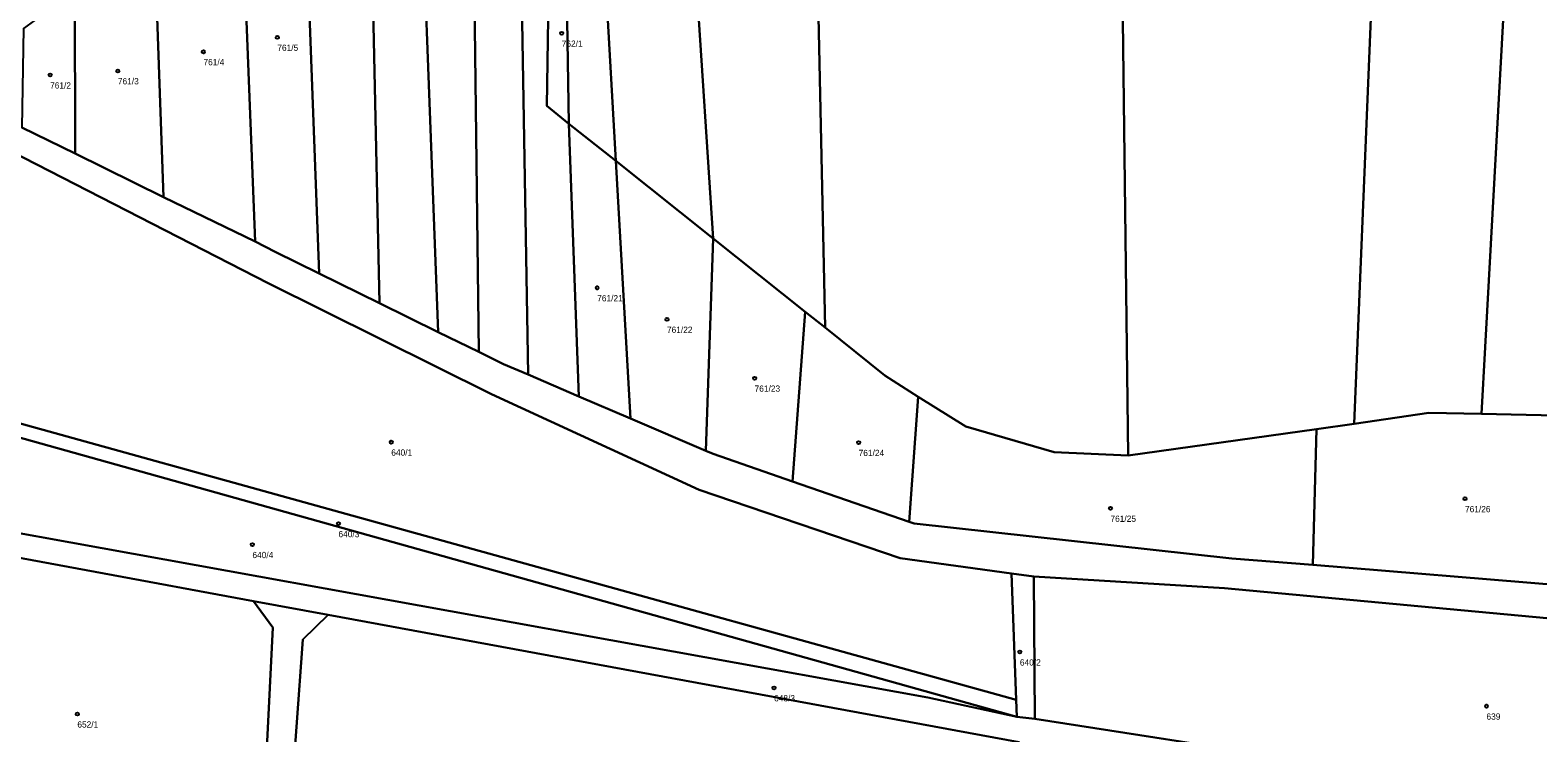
# Model space of a CAD drawing. Extents: x -587171 to -555306, y -1167727 to -1074732.
# Drawn here: x -586119 to -585877.6, y -1165348.1 to -1165235.6 of the extents above; entities that cross this region are included whole.
import ezdxf

# ---------------------------------------------------------------- set-up
doc = ezdxf.new("R2010")
doc.units = 0
doc.layers.add('Definiční body', color=7, linetype='Continuous')
doc.layers.add('Polygon parcely', color=7, linetype='Continuous')

msp = doc.modelspace()

# ---------------------------------------------------------------- linework, layer by layer
at = {"layer": 'Definiční body'}
for centre in [(-586033.93, -1165236.09), (-586079.47, -1165236.74), (-586091.3, -1165239.05), (-586115.85, -1165242.77), (-586105, -1165242.11), (-586028.25, -1165276.85), (-586017.08, -1165281.89), (-586003.05, -1165291.32), (-586061.22, -1165301.55), (-585986.39, -1165301.62), (-585889.3, -1165310.61), (-585946.07, -1165312.15), (-586069.68, -1165314.61), (-586083.46, -1165317.96), (-585960.57, -1165335.16), (-585999.93, -1165340.9), (-585885.86, -1165343.83), (-586111.49, -1165345.09)]:
    msp.add_circle(centre, 0.25, dxfattribs=at)
at = {"layer": 'Polygon parcely'}
for points in [[(-585886.63, -1165297.03), (-585876.95, -1165120.35), (-585894.18, -1165113.04), (-585883.91, -1165096.03), (-585896.44, -1165086.92), (-585882.93, -1165070.13), (-585873.52, -1165060.03), (-585881.75, -1165054.17), (-585897.71, -1165067.32), (-585902.01, -1165176.43), (-585907.05, -1165298.6), (-585895.08, -1165296.86)], [(-585907.05, -1165298.6), (-585902.01, -1165176.43), (-585897.71, -1165067.32), (-585909.33, -1165075.43), (-585909.82, -1165089.08), (-585929.67, -1165104.07), (-585945.54, -1165116.26), (-585943.24, -1165303.67), (-585913.05, -1165299.45)], [(-585978.48, -1165138.78), (-585981.42, -1165148.71), (-585993.8, -1165160.54), (-585993.37, -1165208.49), (-585991.77, -1165283.22), (-585982.19, -1165290.86), (-585976.85, -1165294.27), (-585969.25, -1165299.02), (-585955.07, -1165303.18), (-585943.24, -1165303.67), (-585945.54, -1165116.26), (-585965.05, -1165130.07)], [(-585864.03, -1165297.55), (-585856.06, -1165132.46), (-585873.96, -1165121.53), (-585876.95, -1165120.35), (-585886.63, -1165297.03), (-585872.33, -1165297.33)], [(-585993.37, -1165208.49), (-585993.8, -1165160.54), (-586000.81, -1165166.93), (-586005.94, -1165171.23), (-586011.22, -1165175.11), (-586011.11, -1165180.26), (-586012.43, -1165227.35), (-586009.68, -1165268.95), (-585994.93, -1165280.7), (-585991.77, -1165283.22)], [(-586033.79, -1165190.21), (-586034.18, -1165166.72), (-586040.52, -1165172.08), (-586040.27, -1165234.18), (-586039.3, -1165290.74), (-586031.18, -1165294.22), (-586032.77, -1165250.56), (-586036.34, -1165247.72), (-586035.46, -1165191.62)], [(-586039.3, -1165290.74), (-586040.27, -1165234.18), (-586040.52, -1165172.08), (-586048.55, -1165178.86), (-586047.22, -1165287.1), (-586043.25, -1165289.05)], [(-586047.22, -1165287.1), (-586048.55, -1165178.86), (-586057.39, -1165186.33), (-586053.71, -1165283.92)], [(-586012.43, -1165227.35), (-586011.11, -1165180.26), (-586026.17, -1165189.55), (-586026.83, -1165229.24), (-586025.28, -1165256.53), (-586009.68, -1165268.95)], [(-586057.39, -1165186.33), (-586064.99, -1165192.75), (-586063.1, -1165279.31), (-586053.71, -1165283.92)], [(-586025.28, -1165256.53), (-586026.83, -1165229.24), (-586026.17, -1165189.55), (-586033.72, -1165194.21), (-586032.77, -1165250.56)], [(-586036.34, -1165247.72), (-586032.77, -1165250.56), (-586033.72, -1165194.21), (-586033.79, -1165190.21), (-586035.46, -1165191.62)], [(-586063.1, -1165279.31), (-586064.99, -1165192.75), (-586075.49, -1165201.63), (-586072.78, -1165274.55)], [(-586072.78, -1165274.55), (-586075.49, -1165201.63), (-586082.38, -1165207.46), (-586085.35, -1165209.65), (-586083.03, -1165269.44), (-586079.8, -1165271.1)], [(-586083.03, -1165269.44), (-586085.35, -1165209.65), (-586099.19, -1165219.88), (-586097.7, -1165262.31)], [(-586097.7, -1165262.31), (-586099.19, -1165219.88), (-586111.91, -1165229.28), (-586111.83, -1165255.36)], [(-586111.83, -1165255.36), (-586111.91, -1165229.28), (-586120.11, -1165235.33), (-586120.4, -1165251.15)], [(-585961.16, -1165342.8), (-585961.9, -1165322.59), (-585979.72, -1165320.1), (-586011.93, -1165309.16), (-586045.19, -1165293.88), (-586080.96, -1165276.08), (-586142.78, -1165244.37), (-586142.51, -1165291.18), (-586142.77, -1165292.42)], [(-586022.93, -1165297.76), (-586025.28, -1165256.53), (-586032.77, -1165250.56), (-586031.18, -1165294.22)], [(-586025.28, -1165256.53), (-586022.93, -1165297.76), (-586010.87, -1165302.94), (-586009.68, -1165268.95)], [(-585997, -1165307.83), (-585994.93, -1165280.7), (-586009.68, -1165268.95), (-586010.87, -1165302.94), (-586009.69, -1165303.44)], [(-585982.19, -1165290.86), (-585991.77, -1165283.22), (-585994.93, -1165280.7), (-585997, -1165307.83), (-585978.32, -1165314.29), (-585976.85, -1165294.27)], [(-585961.06, -1165345.54), (-585961.16, -1165342.8), (-586142.77, -1165292.42), (-586143.09, -1165293.97), (-586143.12, -1165294.54)], [(-585975.3, -1165342.45), (-585961.06, -1165345.54), (-586143.12, -1165294.54), (-586143.87, -1165307.19), (-586138.24, -1165312.97)], [(-585976.85, -1165294.27), (-585978.32, -1165314.29), (-585977.52, -1165314.56), (-585926.65, -1165320.16), (-585913.67, -1165321.21), (-585913.05, -1165299.45), (-585943.24, -1165303.67), (-585955.07, -1165303.18), (-585969.25, -1165299.02)], [(-585886.63, -1165297.03), (-585895.08, -1165296.86), (-585907.05, -1165298.6), (-585913.05, -1165299.45), (-585913.67, -1165321.21), (-585873.6, -1165324.52), (-585872.33, -1165297.33)], [(-586081.68, -1165361.28), (-586080.2, -1165331.23), (-586083.27, -1165326.99), (-586134.04, -1165317.64), (-586143.59, -1165319.91), (-586143.6, -1165356.65)], [(-585961.16, -1165342.8), (-585961.06, -1165345.54), (-585958.17, -1165345.86), (-585958.32, -1165323.06), (-585961.9, -1165322.59)], [(-585958.17, -1165345.86), (-585873.1, -1165359.09), (-585824.59, -1165365), (-585819.46, -1165334.58), (-585869.32, -1165330.37), (-585927.79, -1165324.91), (-585958.32, -1165323.06)], [(-586091.89, -1165639.57), (-586096.19, -1165633.62), (-586096.01, -1165627.96), (-586094.44, -1165605.85), (-586093.01, -1165583.46), (-586091.55, -1165561.99), (-586090.27, -1165539.5), (-586088.56, -1165516.12), (-586086.71, -1165493.53), (-586085.42, -1165470.29), (-586083.85, -1165447.07), (-586082.14, -1165422.97), (-586080.33, -1165399.58), (-586078.43, -1165375.1), (-586075.4, -1165333.14), (-586071.33, -1165329.19), (-586083.27, -1165326.99), (-586080.2, -1165331.23), (-586081.68, -1165361.28), (-586083.58, -1165385.43), (-586089.97, -1165469.2), (-586102.07, -1165633.68), (-586106.67, -1165638.83)], [(-585961.24, -1165382.66), (-585960.69, -1165349.57), (-586071.33, -1165329.19), (-586075.4, -1165333.14), (-586078.43, -1165375.1)]]:
    msp.add_lwpolyline(points, close=True, dxfattribs=at)
for points in [[(-586142.78, -1165244.37), (-586080.96, -1165276.08), (-586045.19, -1165293.88), (-586011.93, -1165309.16), (-585979.72, -1165320.1), (-585961.9, -1165322.59), (-585958.32, -1165323.06), (-585927.79, -1165324.91), (-585869.32, -1165330.37), (-585819.46, -1165334.58), (-585779.75, -1165338.59), (-585711.71, -1165348.16), (-585711.38, -1165345.87), (-585682.04, -1165350.2)], [(-585873.6, -1165324.52), (-585913.67, -1165321.21), (-585926.65, -1165320.16), (-585977.52, -1165314.56), (-585978.32, -1165314.29), (-585997, -1165307.83), (-586009.69, -1165303.44), (-586010.87, -1165302.94), (-586022.93, -1165297.76), (-586031.18, -1165294.22), (-586039.3, -1165290.74), (-586043.25, -1165289.05), (-586047.22, -1165287.1), (-586053.71, -1165283.92), (-586063.1, -1165279.31), (-586072.78, -1165274.55), (-586079.8, -1165271.1), (-586083.03, -1165269.44), (-586097.7, -1165262.31), (-586111.83, -1165255.36), (-586120.4, -1165251.15)], [(-585873.1, -1165359.09), (-585958.17, -1165345.86), (-585961.06, -1165345.54), (-585975.3, -1165342.45), (-586138.24, -1165312.97)], [(-586134.04, -1165317.64), (-586083.27, -1165326.99), (-586071.33, -1165329.19), (-585960.69, -1165349.57)]]:
    msp.add_lwpolyline(points, dxfattribs=at)

# ---------------------------------------------------------------- texts
at = {"layer": 'Definiční body'}
for s, p in [('761/5', (-586079.47, -1165238.9)), ('762/1', (-586033.93, -1165238.25)), ('761/4', (-586091.3, -1165241.21)), ('761/3', (-586105, -1165244.27)), ('761/2', (-586115.85, -1165244.93)), ('761/21', (-586028.25, -1165279.01)), ('761/22', (-586017.08, -1165284.05)), ('761/23', (-586003.05, -1165293.48)), ('640/1', (-586061.22, -1165303.71)), ('761/24', (-585986.39, -1165303.78)), ('761/25', (-585946.07, -1165314.31)), ('761/26', (-585889.3, -1165312.77)), ('640/3', (-586069.68, -1165316.77)), ('640/4', (-586083.46, -1165320.12)), ('640/2', (-585960.57, -1165337.32)), ('648/3', (-585999.93, -1165343.06)), ('652/1', (-586111.49, -1165347.25)), ('639', (-585885.86, -1165345.99))]:
    msp.add_text(s, height=1, dxfattribs=at).set_placement(p)

doc.saveas('drawing.dxf')
